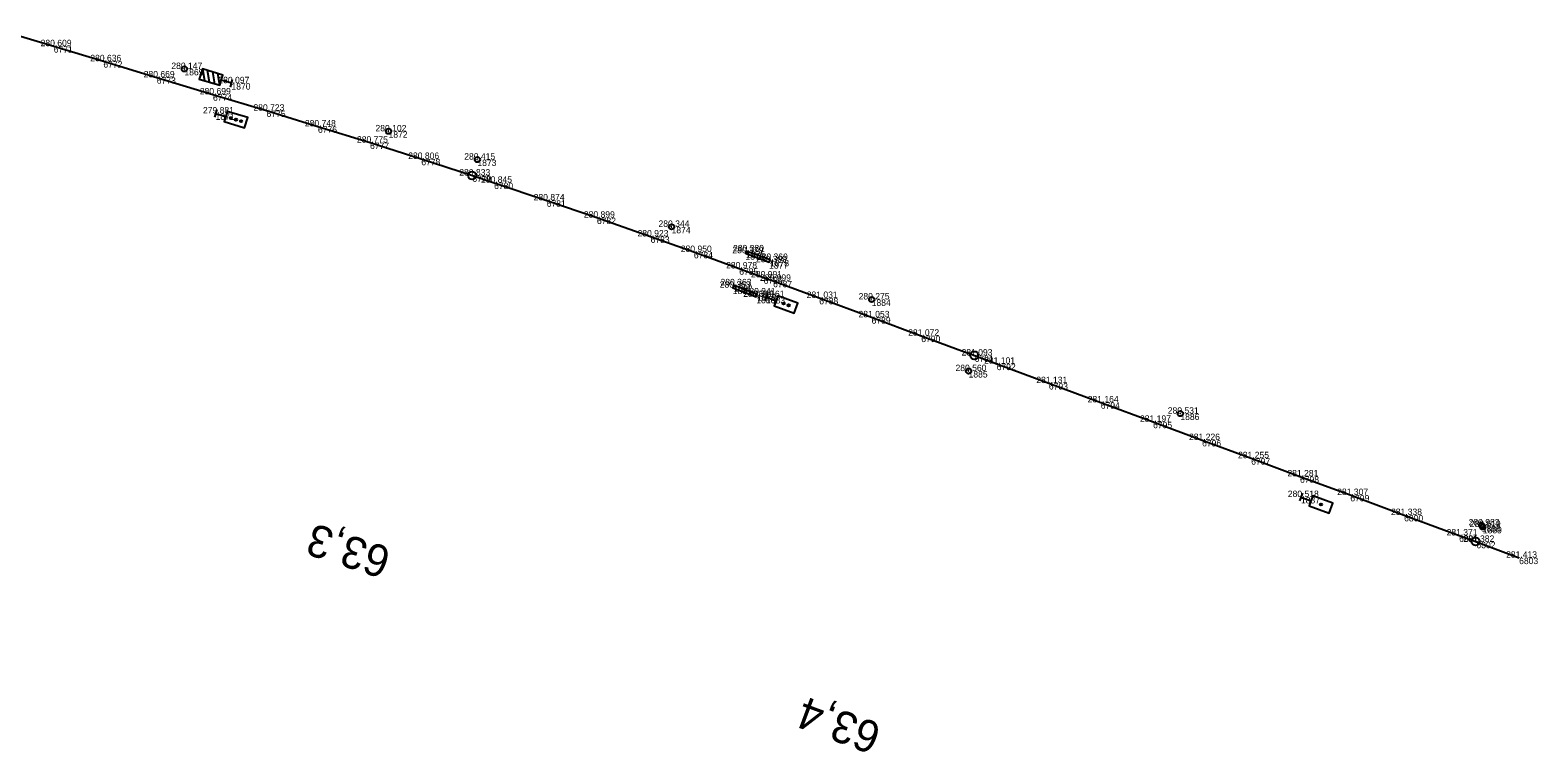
# Model space of a CAD drawing. Extents: x -613968 to -612840, y -1056667 to -1056202.
# Drawn here: x -613122.4 to -612839.8, y -1056667.4 to -1056532 of the extents above; entities that cross this region are included whole.
import ezdxf

# ---------------------------------------------------------------- set-up
doc = ezdxf.new("R2010")
doc.units = 0
for name, color, linetype in [('Rozpiska_pole_7', 7, 'Continuous'), ('Vrstva 1', 7, 'Continuous'), ('Vrstva 19', 7, 'Continuous'), ('Vrstva 50', 7, 'Continuous'), ('Vrstva 60', 7, 'Continuous'), ('Vrstva 61', 7, 'Continuous')]:
    doc.layers.add(name, color=color, linetype=linetype)

msp = doc.modelspace()

# ---------------------------------------------------------------- linework, layer by layer
at = {"layer": 'Rozpiska_pole_7'}
for p, q in [((-613090.09, -1056539.26), (-613089.71, -1056541.46)), ((-613088.75, -1056541.75), (-613089.13, -1056539.55)), ((-613088.17, -1056539.84), (-613087.8, -1056542.05)), ((-613086.84, -1056542.34), (-613087.22, -1056540.13)), ((-613084.85, -1056542.68), (-613084.42, -1056541.24)), ((-613087.4, -1056546.9), (-613087.84, -1056548.33)), ((-613084.66, -1056548.66), (-613084.85, -1056548.31)), ((-613083.7, -1056548.95), (-613083.89, -1056548.6)), ((-613082.74, -1056549.24), (-613082.92, -1056548.89)), ((-613038.6, -1056556.26), (-613038.51, -1056556.29)), ((-612984.17, -1056581.31), (-612984.69, -1056582.72)), ((-612981.06, -1056583.4), (-612981.22, -1056583.04)), ((-612980.13, -1056583.75), (-612980.29, -1056583.39)), ((-612946.53, -1056595.87), (-612946.44, -1056595.9)), ((-612883.92, -1056618.77), (-612884.44, -1056620.18)), ((-612880.35, -1056621.05), (-612880.51, -1056620.69)), ((-612850.35, -1056624.77), (-612850.25, -1056624.81))]:
    msp.add_line(p, q, dxfattribs=at)
for points in [[(-613084.64, -1056541.96), (-613086.55, -1056541.38), (-613086.26, -1056540.42), (-613090.09, -1056539.26), (-613090.67, -1056541.17), (-613086.84, -1056542.34), (-613086.55, -1056541.38)], [(-613087.62, -1056547.62), (-613085.71, -1056548.2), (-613086, -1056549.16), (-613082.17, -1056550.32), (-613081.59, -1056548.4), (-613085.42, -1056547.24), (-613085.71, -1056548.2)], [(-612984.43, -1056582.02), (-612982.56, -1056582.71), (-612982.9, -1056583.65), (-612979.15, -1056585.03), (-612978.46, -1056583.16), (-612982.21, -1056581.77), (-612982.56, -1056582.71)], [(-612884.18, -1056619.48), (-612882.31, -1056620.17), (-612882.65, -1056621.11), (-612878.9, -1056622.5), (-612878.21, -1056620.63), (-612881.96, -1056619.24), (-612882.31, -1056620.17)]]:
    msp.add_lwpolyline(points, dxfattribs=at)
for centre, radius in [((-613084.75, -1056548.49), 0.2), ((-613083.8, -1056548.78), 0.2), ((-613082.84, -1056549.07), 0.2), ((-613039.55, -1056559.23), 0.75), ((-613038.55, -1056556.27), 0.5), ((-612981.15, -1056583.23), 0.2), ((-612980.21, -1056583.57), 0.2), ((-612945.42, -1056592.94), 0.75), ((-612946.48, -1056595.89), 0.5), ((-612880.43, -1056620.87), 0.2), ((-612850.3, -1056624.79), 0.5), ((-612851.44, -1056627.83), 0.75)]:
    msp.add_circle(centre, radius, dxfattribs=at)
at = {"layer": 'Vrstva 1'}
msp.add_lwpolyline([(-613127.92, -1056532.02), (-613117.96, -1056535.02), (-613108.65, -1056537.84), (-613098.64, -1056540.86), (-613088.11, -1056544.05), (-613078.07, -1056547.1), (-613068.43, -1056550.05), (-613058.67, -1056553.09), (-613049.06, -1056556.14), (-613039.49, -1056559.25), (-613035.41, -1056560.59), (-613025.55, -1056563.91), (-613016.14, -1056567.14), (-613006.08, -1056570.67), (-612997.97, -1056573.57), (-612989.47, -1056576.66), (-612984.89, -1056578.33), (-612983.12, -1056578.98), (-612974.47, -1056582.18), (-612964.66, -1056585.81), (-612955.35, -1056589.26), (-612945.34, -1056592.97), (-612941.21, -1056594.51), (-612931.43, -1056598.14), (-612921.7, -1056601.75), (-612911.9, -1056605.39), (-612902.71, -1056608.8), (-612893.51, -1056612.21), (-612884.36, -1056615.61), (-612874.93, -1056619.1), (-612864.84, -1056622.85), (-612854.53, -1056626.68), (-612851.29, -1056627.88), (-612843.28, -1056630.85)], dxfattribs=at)
at = {"layer": 'Vrstva 19'}
for points in [[(-612988.19, -1056573.45), (-612988.3, -1056573.81), (-612983.87, -1056575.49), (-612983.7, -1056575.06)], [(-612990.52, -1056579.81), (-612990.67, -1056580.26), (-612986.27, -1056581.98), (-612986.1, -1056581.51)]]:
    msp.add_lwpolyline(points, close=True, dxfattribs=at)
at = {"layer": 'Vrstva 50'}
for p, q in [((-613093.51, -1056539.28), (-613093.41, -1056539.31)), ((-613055.25, -1056550.96), (-613055.16, -1056550.99)), ((-613002.2, -1056568.85), (-613002.1, -1056568.89)), ((-612964.68, -1056582.45), (-612964.59, -1056582.49)), ((-612906.83, -1056603.84), (-612906.74, -1056603.87)), ((-612850.14, -1056625.06), (-612850.05, -1056625.1))]:
    msp.add_line(p, q, dxfattribs=at)
for centre in [(-613093.46, -1056539.29), (-613055.2, -1056550.97), (-613002.15, -1056568.87), (-612964.64, -1056582.47), (-612906.78, -1056603.86), (-612850.09, -1056625.08)]:
    msp.add_circle(centre, 0.5, dxfattribs=at)
at = {"layer": 'Vrstva 60'}
for p, q in [((-613117.96, -1056535.02), (-613117.96, -1056535.02)), ((-613108.65, -1056537.84), (-613108.65, -1056537.84)), ((-613098.64, -1056540.86), (-613098.64, -1056540.86)), ((-613093.46, -1056539.29), (-613093.46, -1056539.29)), ((-613088.11, -1056544.05), (-613088.11, -1056544.05)), ((-613084.64, -1056541.96), (-613084.64, -1056541.96)), ((-613078.07, -1056547.1), (-613078.07, -1056547.1)), ((-613087.62, -1056547.62), (-613087.62, -1056547.62)), ((-613068.43, -1056550.05), (-613068.43, -1056550.05)), ((-613055.2, -1056550.97), (-613055.2, -1056550.97)), ((-613058.67, -1056553.09), (-613058.67, -1056553.09)), ((-613049.06, -1056556.14), (-613049.06, -1056556.14)), ((-613038.55, -1056556.27), (-613038.55, -1056556.27)), ((-613039.49, -1056559.25), (-613039.49, -1056559.25)), ((-613035.41, -1056560.59), (-613035.41, -1056560.59)), ((-613025.55, -1056563.91), (-613025.55, -1056563.91)), ((-613016.14, -1056567.14), (-613016.14, -1056567.14)), ((-613002.15, -1056568.87), (-613002.15, -1056568.87)), ((-613006.08, -1056570.67), (-613006.08, -1056570.67)), ((-612997.97, -1056573.57), (-612997.97, -1056573.57)), ((-612988.3, -1056573.81), (-612988.3, -1056573.81)), ((-612988.19, -1056573.45), (-612988.19, -1056573.45)), ((-612983.87, -1056575.49), (-612983.87, -1056575.49)), ((-612983.7, -1056575.06), (-612983.7, -1056575.06)), ((-612989.47, -1056576.66), (-612989.47, -1056576.66)), ((-612984.89, -1056578.33), (-612984.89, -1056578.33)), ((-612990.67, -1056580.26), (-612990.67, -1056580.26)), ((-612990.52, -1056579.81), (-612990.52, -1056579.81)), ((-612983.12, -1056578.98), (-612983.12, -1056578.98)), ((-612986.27, -1056581.98), (-612986.27, -1056581.98)), ((-612986.1, -1056581.51), (-612986.1, -1056581.51)), ((-612984.43, -1056582.02), (-612984.43, -1056582.02)), ((-612974.47, -1056582.18), (-612974.47, -1056582.18)), ((-612964.64, -1056582.47), (-612964.64, -1056582.47)), ((-612964.66, -1056585.81), (-612964.66, -1056585.81)), ((-612955.35, -1056589.26), (-612955.35, -1056589.26)), ((-612945.34, -1056592.97), (-612945.34, -1056592.97)), ((-612941.21, -1056594.51), (-612941.21, -1056594.51)), ((-612946.48, -1056595.89), (-612946.48, -1056595.89)), ((-612931.43, -1056598.14), (-612931.43, -1056598.14)), ((-612921.7, -1056601.75), (-612921.7, -1056601.75)), ((-612911.9, -1056605.39), (-612911.9, -1056605.39)), ((-612906.78, -1056603.86), (-612906.78, -1056603.86)), ((-612902.71, -1056608.8), (-612902.71, -1056608.8)), ((-612893.51, -1056612.21), (-612893.51, -1056612.21)), ((-612884.36, -1056615.61), (-612884.36, -1056615.61)), ((-612884.18, -1056619.48), (-612884.18, -1056619.48)), ((-612874.93, -1056619.1), (-612874.93, -1056619.1)), ((-612864.84, -1056622.85), (-612864.84, -1056622.85)), ((-612850.3, -1056624.79), (-612850.3, -1056624.79)), ((-612850.09, -1056625.08), (-612850.09, -1056625.08)), ((-612854.53, -1056626.68), (-612854.53, -1056626.68)), ((-612851.29, -1056627.88), (-612851.29, -1056627.88)), ((-612843.28, -1056630.85), (-612843.28, -1056630.85))]:
    msp.add_line(p, q, dxfattribs=at)

# ---------------------------------------------------------------- texts
at = {"layer": 'Rozpiska_pole_7'}
for s, rotation, p in [('63,3', 161.9883, (-613054.39, -1056629.17)), ('63,4', 159.6437, (-612962.46, -1056662.19))]:
    msp.add_text(s, height=6, rotation=rotation, dxfattribs=at).set_placement(p)
at = {"layer": 'Vrstva 60'}
for s, p in [('6771', (-613117.96, -1056536.22)), ('6772', (-613108.65, -1056539.04)), ('6773', (-613098.64, -1056542.06)), ('1869', (-613093.46, -1056540.49)), ('6774', (-613088.11, -1056545.25)), ('1870', (-613084.64, -1056543.16)), ('6775', (-613078.07, -1056548.3)), ('1871', (-613087.62, -1056548.82)), ('6776', (-613068.43, -1056551.25)), ('1872', (-613055.2, -1056552.17)), ('6777', (-613058.67, -1056554.29)), ('6778', (-613049.06, -1056557.33)), ('1873', (-613038.55, -1056557.47)), ('6779', (-613039.49, -1056560.45)), ('6780', (-613035.41, -1056561.79)), ('6781', (-613025.55, -1056565.11)), ('6782', (-613016.14, -1056568.34)), ('1874', (-613002.15, -1056570.07)), ('6783', (-613006.08, -1056571.87)), ('6784', (-612997.97, -1056574.77)), ('1876', (-612988.3, -1056575.01)), ('1875', (-612988.19, -1056574.65)), ('1877', (-612983.87, -1056576.69)), ('1878', (-612983.7, -1056576.26)), ('6785', (-612989.47, -1056577.86)), ('6786', (-612984.89, -1056579.53)), ('1881', (-612990.67, -1056581.46)), ('1882', (-612990.52, -1056581.01)), ('6787', (-612983.12, -1056580.18)), ('1880', (-612986.27, -1056583.18)), ('1879', (-612986.1, -1056582.71)), ('1883', (-612984.43, -1056583.22)), ('6788', (-612974.47, -1056583.38)), ('1884', (-612964.64, -1056583.67)), ('6789', (-612964.66, -1056587.01)), ('6790', (-612955.35, -1056590.46)), ('6791', (-612945.34, -1056594.17)), ('6792', (-612941.21, -1056595.71)), ('1885', (-612946.48, -1056597.09)), ('6793', (-612931.43, -1056599.34)), ('6794', (-612921.7, -1056602.95)), ('6795', (-612911.9, -1056606.59)), ('1886', (-612906.78, -1056605.06)), ('6796', (-612902.71, -1056610)), ('6797', (-612893.51, -1056613.41)), ('6798', (-612884.36, -1056616.81)), ('1887', (-612884.18, -1056620.68)), ('6799', (-612874.93, -1056620.3)), ('6800', (-612864.84, -1056624.05)), ('1888', (-612850.3, -1056625.99)), ('1889', (-612850.09, -1056626.28)), ('6801', (-612854.53, -1056627.88)), ('6802', (-612851.29, -1056629.08)), ('6803', (-612843.28, -1056632.05))]:
    msp.add_text(s, height=1.2, dxfattribs=at).set_placement(p)
at = {"layer": 'Vrstva 61'}
for s, p in [('280.609', (-613120.41, -1056535.02)), ('280.636', (-613111.1, -1056537.84)), ('280.147', (-613095.91, -1056539.29)), ('280.669', (-613101.09, -1056540.86)), ('280.097', (-613087.09, -1056541.96)), ('280.699', (-613090.57, -1056544.05)), ('279.881', (-613089.98, -1056547.62)), ('280.723', (-613080.52, -1056547.1)), ('280.748', (-613070.88, -1056550.05)), ('280.102', (-613057.65, -1056550.97)), ('280.775', (-613061.12, -1056553.09)), ('280.806', (-613051.51, -1056556.14)), ('280.415', (-613041.01, -1056556.27)), ('280.833', (-613041.94, -1056559.25)), ('280.845', (-613037.86, -1056560.59)), ('280.874', (-613028, -1056563.91)), ('280.899', (-613018.59, -1056567.14)), ('280.923', (-613008.53, -1056570.67)), ('280.344', (-613004.6, -1056568.87)), ('280.950', (-613000.42, -1056573.57)), ('280.379', (-612990.75, -1056573.81)), ('280.380', (-612990.64, -1056573.45)), ('280.978', (-612991.93, -1056576.66)), ('280.399', (-612986.32, -1056575.49)), ('280.369', (-612986.16, -1056575.06)), ('280.991', (-612987.25, -1056578.33)), ('280.999', (-612985.58, -1056578.98)), ('280.363', (-612993.12, -1056580.26)), ('280.363', (-612992.97, -1056579.81)), ('280.349', (-612988.72, -1056581.98)), ('280.341', (-612988.46, -1056581.51)), ('280.161', (-612986.79, -1056582.02)), ('281.031', (-612976.82, -1056582.18)), ('280.275', (-612967.09, -1056582.47)), ('281.053', (-612967.11, -1056585.81)), ('281.072', (-612957.8, -1056589.26)), ('281.093', (-612947.8, -1056592.97)), ('280.560', (-612948.93, -1056595.89)), ('281.101', (-612943.57, -1056594.51)), ('281.131', (-612933.78, -1056598.14)), ('281.164', (-612924.15, -1056601.75)), ('280.531', (-612909.14, -1056603.86)), ('281.197', (-612914.35, -1056605.39)), ('281.226', (-612905.16, -1056608.8)), ('281.255', (-612895.97, -1056612.21)), ('281.281', (-612886.72, -1056615.61)), ('281.307', (-612877.39, -1056619.1)), ('280.518', (-612886.64, -1056619.48)), ('281.338', (-612867.3, -1056622.85)), ('280.983', (-612852.75, -1056624.79)), ('281.371', (-612856.88, -1056626.68)), ('280.619', (-612852.55, -1056625.08)), ('281.382', (-612853.74, -1056627.88)), ('281.413', (-612845.73, -1056630.85))]:
    msp.add_text(s, height=1.2, dxfattribs=at).set_placement(p)

doc.saveas('drawing.dxf')
